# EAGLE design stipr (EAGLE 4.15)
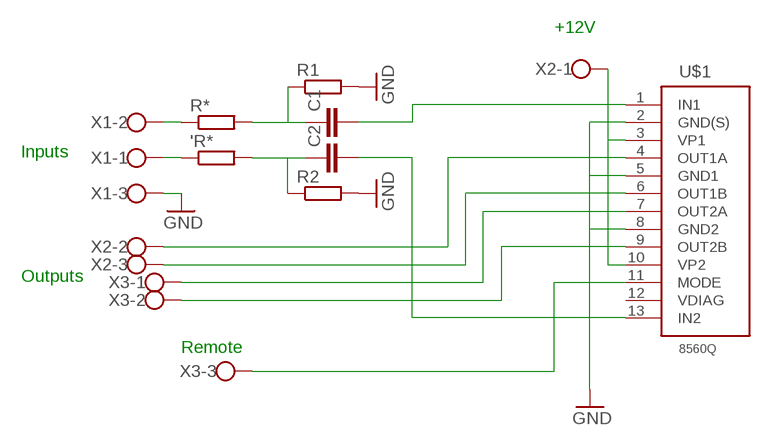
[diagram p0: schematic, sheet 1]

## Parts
'R*  R-EU_0207/10  [0207/10]
C1  C-EU050-025X075  [C050-025X075]
C2  C-EU050-025X075  [C050-025X075]
R1  R-EU_0207/10  [0207/10]
R2  R-EU_0207/10  [0207/10]
R*  R-EU_0207/10  [0207/10]
U$1  8560Q  [SOT141-6]
X1  W237-3E  [W237-3E]
X2  W237-3E  [W237-3E]
X3  W237-3E  [W237-3E]

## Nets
GND: R1.2 R2.2 U$1.2(GND(S)) U$1.5(GND1) U$1.8(GND2) X1.3
N$1: C1.1 R1.1 R*.2
N$2: 'R*.2 C2.1 R2.1
N$3: C1.2 U$1.1(IN1)
N$4: C2.2 U$1.13(IN2)
N$5: U$1.3(VP1) U$1.10(VP2) X2.1
N$6: 'R*.1 X1.1
N$7: R*.1 X1.2
N$8: U$1.4(OUT1A) X2.2
N$9: U$1.6(OUT1B) X2.3
N$10: U$1.7(OUT2A) X3.1
N$11: U$1.9(OUT2B) X3.2
N$12: U$1.11(MODE) X3.3
Unconnected: U$1.12(VDIAG)

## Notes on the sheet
- +12V
- Inputs
- Outputs
- Remote

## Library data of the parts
'R* R1 R2 R* = rcl:R-EU_: RESISTOR, European symbol
C1 C2 = rcl:C-EU: CAPACITOR, European symbol
U$1 = tda8560q:8560Q: 2x40W Stereo BTL Amplifier
X1-X3 = con-wago-508:W237-3E: WAGO SREW CLAMP

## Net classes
0 default: width 1.27 mm, drill 0.508 mm

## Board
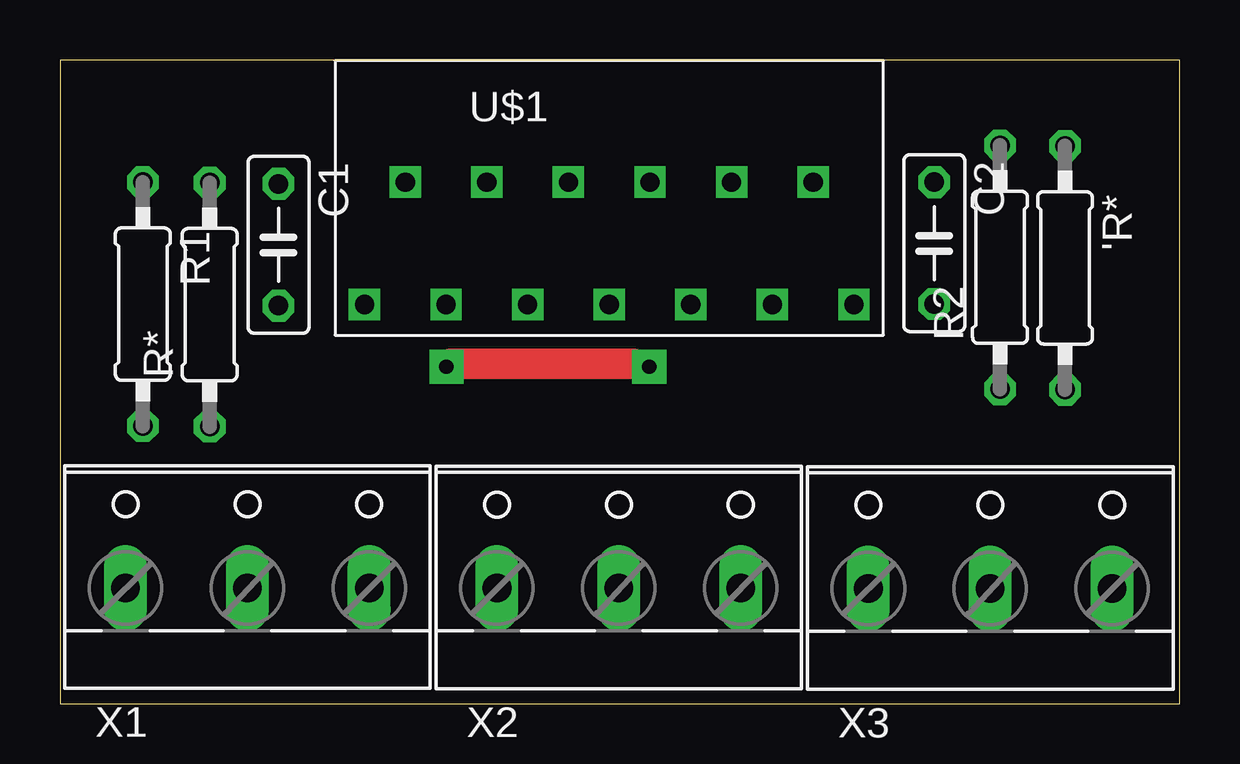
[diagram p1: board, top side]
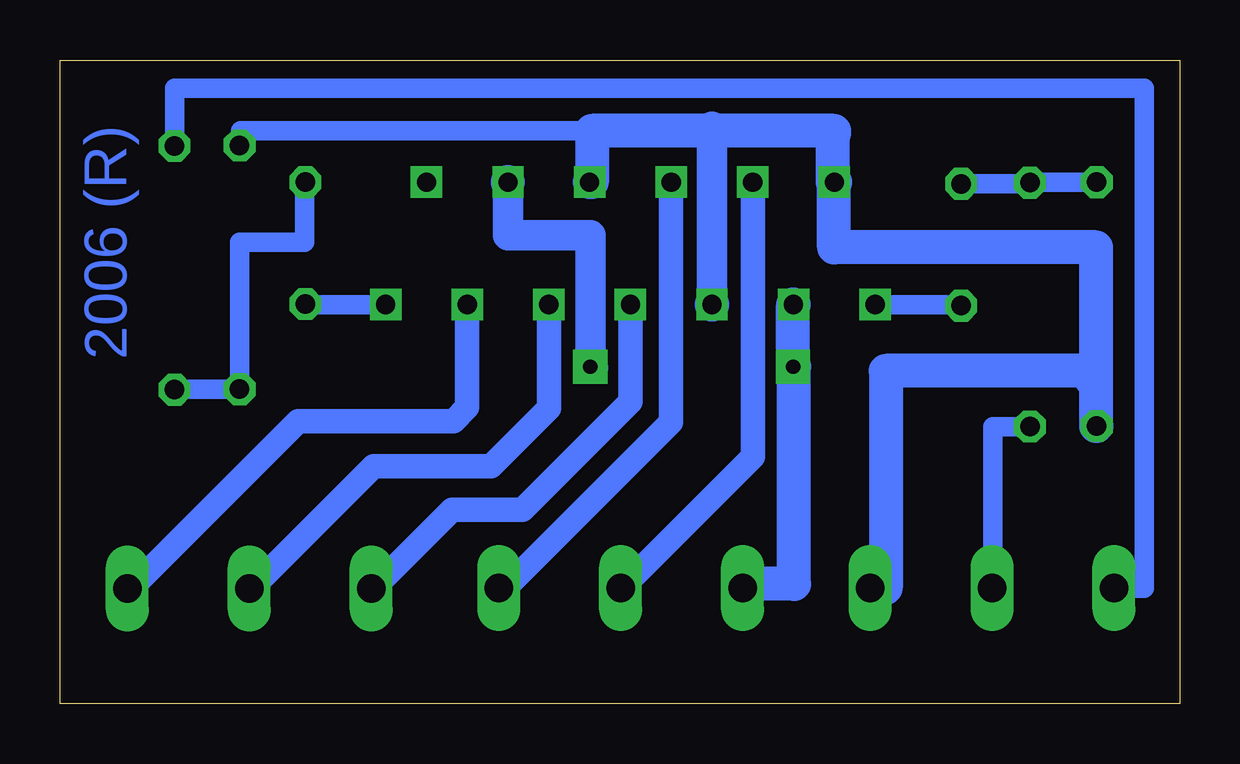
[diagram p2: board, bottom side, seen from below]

Size 46.67 x 26.82 mm. Coordinates in mm from the lower left corner, seen from the top.
Outline: 0,0 46.67,0 46.67,26.82 0,26.82 0,0
Copper layers (1*16): Top 0.035mm / dielectric 1.5mm / Bottom 0.035mm
Design rules "default": minimum track width 10mil, minimum drill 24mil, track to track 8mil, track to pad 8mil, pad to pad 8mil, via to via 8mil, smd to smd 8mil, copper to edge 40mil, drill to drill 8mil, minimum pad ring 10mil, minimum via ring 8mil, stop-mask expansion 4mil, vias tented up to drill 0mil, thermal gap 10mil

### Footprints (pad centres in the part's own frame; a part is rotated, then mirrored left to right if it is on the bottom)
0207/10 = drill 0.813 octagon: 1 -5.08,0; 2 5.08,0
C050-025X075 = drill 0.813 octagon: 1 -2.54,0; 2 2.54,0
SOT141-6 = drill 0.8 square: 1 -10.2,-3.81; 2 -8.5,1.29; 3 -6.8,-3.81; 4 -5.1,1.29; 5 -3.4,-3.81; 6 -1.7,1.29; 7 0,-3.81; 8 1.7,1.29; 9 3.4,-3.81; 10 5.1,1.29; 11 6.8,-3.81; 12 8.5,1.29; 13 10.2,-3.81
W237-3E = drill 1.194 long: 1 -5.08,-0.635; 2 0,-0.635; 3 5.08,-0.635

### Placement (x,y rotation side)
'R*  41.89,18.16 270 top
C1  9.11,19.12 270 top
C2  36.44,19.19 270 top
R1  3.45,16.65 270 top
R2  39.18,18.19 90 top
R*  6.24,16.63 90 top
U$1  22.89,20.44 0 top
X1  7.81,5.46 0 top
X2  23.3,5.45 0 top
X3  38.78,5.44 0 top

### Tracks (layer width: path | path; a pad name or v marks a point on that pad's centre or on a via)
GND
  Bottom 0.813: R1.2 3.53,11.57 | 14.35,21.73 U$1.2 | R2.2 39.13,23.27 39.13,23.87 24.54,23.87 | 24.5,23.87 24.54,23.87 | 24.54,23.87 24.54,23.93 | 3.43,13.35 3.53,13.35
  Bottom 1.27: 19.49,23.87 19.49,24.04 | 19.49,24.04 U$1.5 | 19.49,24.04 19.5,24.05
  Bottom 1.422: U$1.5 | U$1.2 14.45,21.73 14.45,23.77 14.4,23.77 14.4,23.87 19.49,23.87 24.5,23.87 24.5,21.73 U$1.8 | 14.35,21.73 U$1.2 14.4,19.02 3.48,19.02 3.48,13.48 | R1.2 3.48,11.57 3.48,13.48 | X1.3 12.25,4.83 12.25,13.87 3.67,13.87 3.67,13.48 3.48,13.48
N$1
  Bottom 0.813: 6.12,21.66 6.12,21.71 R*.2 6.27,21.71 | 6.12,21.66 C1.1 | 6.12,21.66 6.12,21.62 | 6.27,21.71 6.27,21.67 | R1.1 6.27,21.73 6.27,21.71
N$2
  Bottom 0.813: C2.1 36.48,21.73 36.48,19.23 39.19,19.23 R2.1 | R2.1 39.19,12.93 | R2.1 | 42.01,13.08 42.01,12.93 | 42.01,13.08 'R*.2 | R2.1 42.01,13.11 42.01,13.08
N$3
  Bottom 0.813: C1.2 9.06,16.58 9.06,16.63 U$1.1
N$4
  Bottom 0.813: 36.48,16.65 36.48,16.7 | 36.48,16.65 C2.2 | U$1.13 36.48,16.63 36.48,16.65
N$5  (via drill 0.6 pad 1.42)
  Top 1.27: v24.56,14.04 23.9,14.17 16.28,14.17 v16.11,14.04
  Bottom 1.27: U$1.10 27.99,19.51 24.56,19.51 24.56,14.12 24.48,14.04 | 24.48,14.04 24.44,14 | v24.56,14.04 24.48,14.04
  Bottom 1.422: U$1.3 16.11,16.63 v16.11,14.04 16.08,14.04 16.08,4.99 18.43,4.99 18.43,4.82 | U$1.10 | 18.43,4.82 | 18.43,4.82 X2.1
N$6
  Bottom 0.813: 'R*.1 | 'R*.1 41.89,25.64 1.47,25.64 1.47,4.81 2.74,4.81 X1.1
N$7
  Bottom 0.813: 7.78,4.83 7.78,4.76 | X1.2 7.78,4.83 | R*.1 7.78,11.55 7.78,4.83
N$8
  Bottom 1.016: 23.3,4.78 23.32,4.76 | X2.2 23.3,4.78 | U$1.4 17.79,10.28 23.3,4.78
N$9
  Bottom 1.016: U$1.6 21.19,11.73 28.36,4.56 28.38,4.58 X2.3 | X2.3
N$10
  Bottom 1.016: U$1.7 22.89,12.58 27.38,8.09 30.32,8.09 33.65,4.76 X3.1
N$11
  Bottom 1.016: U$1.9 26.29,12.32 28.7,9.9 33.6,9.9 38.75,4.76 X3.2
N$12
  Bottom 1.016: U$1.11 29.69,12.35 30.27,11.77 36.73,11.77 43.86,4.64 | 43.86,4.64 43.89,4.61 | 43.86,4.64 X3.3

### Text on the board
Bottom: 2006 (R)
